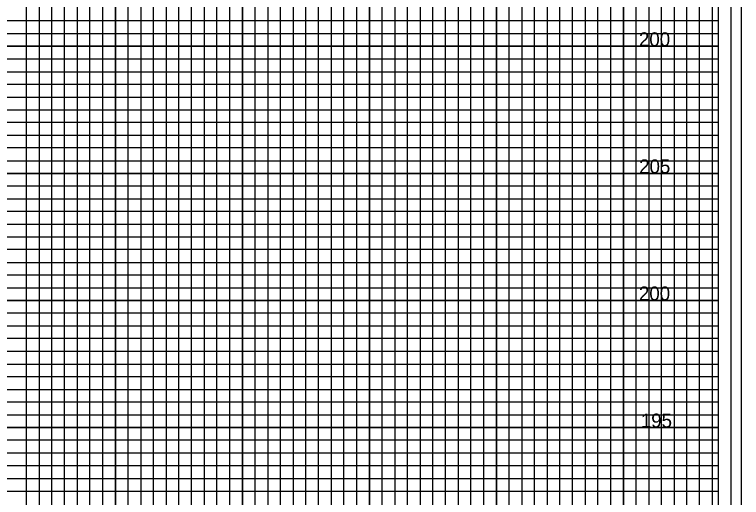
# Model space of a CAD drawing. Extents: x -4 to 103, y -2 to 209.
# Drawn here: x 74.78 to 103.4, y 103.08 to 122.08 of the extents above; entities that cross this region are included whole.
import ezdxf

# ---------------------------------------------------------------- set-up
doc = ezdxf.new("R2010")
doc.units = 0
for name, color, linetype in [('Exist XS Ground Line', 7, 'Continuous'), ('Old_Level_10', 7, 'Continuous'), ('Old_Level_5', 7, 'Continuous'), ('Old_Level_8', 7, 'Continuous'), ('Prop XS Finish Grade Earthwork', 7, 'Continuous'), ('Prop XS Finish Grade Pavement', 7, 'Continuous'), ('Prop XS SE Text', 7, 'Continuous')]:
    doc.layers.add(name, color=color, linetype=linetype)

msp = doc.modelspace()

# ---------------------------------------------------------------- linework, layer by layer
at = {"layer": 'Exist XS Ground Line'}
msp.add_lwpolyline([(103, 136.825), (-2.8, 136.825), (-2.8, 69.825), (103, 69.825)], close=True, dxfattribs=at)
at = {"layer": 'Old_Level_10'}
for p, q in [((91.25, 70.825), (91.25, 134.25)), ((93.75, 70.825), (93.75, 134.25)), ((96.25, 70.825), (96.25, 134.25)), ((98.75, 70.825), (98.75, 134.25)), ((101.25, 70.825), (101.25, 134.25)), ((76.25, 70.825), (76.25, 132.825)), ((78.75, 70.825), (78.75, 132.825)), ((81.25, 70.825), (81.25, 132.825)), ((83.75, 70.825), (83.75, 132.825)), ((86.25, 70.825), (86.25, 132.825)), ((88.75, 70.825), (88.75, 132.825)), ((0, 120.825), (102.5, 120.825)), ((0, 118.325), (102.5, 118.325)), ((0, 115.825), (102.5, 115.825)), ((0, 113.325), (102.5, 113.325)), ((0, 110.825), (102.5, 110.825)), ((0, 108.325), (102.5, 108.325)), ((0, 105.825), (102.5, 105.825)), ((0, 103.325), (102.5, 103.325))]:
    msp.add_line(p, q, dxfattribs=at)
at = {"layer": 'Old_Level_5'}
msp.add_lwpolyline([(103.4, 138.225), (-3.5, 138.225), (-3.5, 68.4), (103.4, 68.4)], close=True, dxfattribs=at)
at = {"layer": 'Old_Level_8'}
for points in [[(91.25, 70.825), (91.25, 134.25), (93.75, 134.25), (93.75, 70.825)], [(96.25, 70.825), (96.25, 134.25), (98.75, 134.25), (98.75, 70.825)], [(101.25, 70.825), (101.25, 134.25)], [(76.25, 70.825), (76.25, 132.825), (78.75, 132.825), (78.75, 70.825)], [(81.25, 70.825), (81.25, 132.825), (83.75, 132.825), (83.75, 70.825)], [(86.25, 70.825), (86.25, 132.825), (88.75, 132.825), (88.75, 70.825)], [(0, 118.325), (102.5, 118.325), (102.5, 120.825), (0, 120.825)], [(0, 113.325), (102.5, 113.325), (102.5, 115.825), (0, 115.825)], [(0, 108.325), (102.5, 108.325), (102.5, 110.825), (0, 110.825)], [(0, 103.325), (102.5, 103.325), (102.5, 105.825), (0, 105.825)]]:
    msp.add_lwpolyline(points, dxfattribs=at)
at = {"layer": 'Prop XS Finish Grade Earthwork'}
for points in [[(90.25, 70.825), (90.25, 134.25), (90.75, 134.25), (90.75, 70.825)], [(91.75, 70.825), (91.75, 134.25), (92.25, 134.25), (92.25, 70.825)], [(92.75, 70.825), (92.75, 134.25), (93.25, 134.25), (93.25, 70.825)], [(94.25, 70.825), (94.25, 134.25), (94.75, 134.25), (94.75, 70.825)], [(95.25, 70.825), (95.25, 134.25), (95.75, 134.25), (95.75, 70.825)], [(96.75, 70.825), (96.75, 134.25), (97.25, 134.25), (97.25, 70.825)], [(97.75, 70.825), (97.75, 134.25), (98.25, 134.25), (98.25, 70.825)], [(99.25, 70.825), (99.25, 134.25), (99.75, 134.25), (99.75, 70.825)], [(100.25, 70.825), (100.25, 134.25)], [(100.25, 134.25), (100.75, 134.25), (100.75, 70.825), (101.75, 70.825), (101.75, 134.25), (102.25, 134.25), (102.25, 70.825)], [(75.25, 70.825), (75.25, 132.825), (75.75, 132.825), (75.75, 70.825)], [(76.75, 70.825), (76.75, 132.825), (77.25, 132.825), (77.25, 70.825)], [(77.75, 70.825), (77.75, 132.825), (78.25, 132.825), (78.25, 70.825)], [(79.25, 70.825), (79.25, 132.825), (79.75, 132.825), (79.75, 70.825)], [(80.25, 70.825), (80.25, 132.825), (80.75, 132.825), (80.75, 70.825)], [(81.75, 70.825), (81.75, 132.825), (82.25, 132.825), (82.25, 70.825)], [(82.75, 70.825), (82.75, 132.825), (83.25, 132.825), (83.25, 70.825)], [(84.25, 70.825), (84.25, 132.825), (84.75, 132.825), (84.75, 70.825)], [(85.25, 70.825), (85.25, 132.825), (85.75, 132.825), (85.75, 70.825)], [(86.75, 70.825), (86.75, 132.825), (87.25, 132.825), (87.25, 70.825)], [(87.75, 70.825), (87.75, 132.825), (88.25, 132.825), (88.25, 70.825)], [(89.25, 70.825), (89.25, 132.825), (89.75, 132.825), (89.75, 70.825)], [(0, 121.325), (102.5, 121.325), (102.5, 121.825), (0, 121.825)], [(0, 119.825), (102.5, 119.825), (102.5, 120.325), (0, 120.325)], [(0, 118.825), (102.5, 118.825), (102.5, 119.325), (0, 119.325)], [(0, 117.325), (102.5, 117.325), (102.5, 117.825), (0, 117.825)], [(0, 116.325), (102.5, 116.325), (102.5, 116.825), (0, 116.825)], [(0, 114.825), (102.5, 114.825), (102.5, 115.325), (0, 115.325)], [(0, 113.825), (102.5, 113.825), (102.5, 114.325), (0, 114.325)], [(0, 112.325), (102.5, 112.325), (102.5, 112.825), (0, 112.825)], [(0, 111.325), (102.5, 111.325), (102.5, 111.825), (0, 111.825)], [(0, 109.825), (102.5, 109.825), (102.5, 110.325), (0, 110.325)], [(0, 108.825), (102.5, 108.825), (102.5, 109.325), (0, 109.325)], [(0, 107.325), (102.5, 107.325), (102.5, 107.825), (0, 107.825)], [(0, 106.325), (102.5, 106.325), (102.5, 106.825), (0, 106.825)], [(0, 104.825), (102.5, 104.825), (102.5, 105.325), (0, 105.325)], [(0, 103.825), (102.5, 103.825), (102.5, 104.325), (0, 104.325)]]:
    msp.add_lwpolyline(points, dxfattribs=at)
at = {"layer": 'Prop XS SE Text'}
msp.add_lwpolyline([(102.5, 135.825), (0, 135.825), (0, 70.825), (102.5, 70.825)], close=True, dxfattribs=at)

# ---------------------------------------------------------------- texts
at = {"layer": 'Prop XS Finish Grade Pavement'}
for s, p in [('200', (99.364, 120.825)), ('205', (99.372, 115.825)), ('200', (99.364, 110.825)), ('195', (99.438, 105.825))]:
    msp.add_text(s, height=0.55, dxfattribs=at).set_placement(p)

doc.saveas('drawing.dxf')
